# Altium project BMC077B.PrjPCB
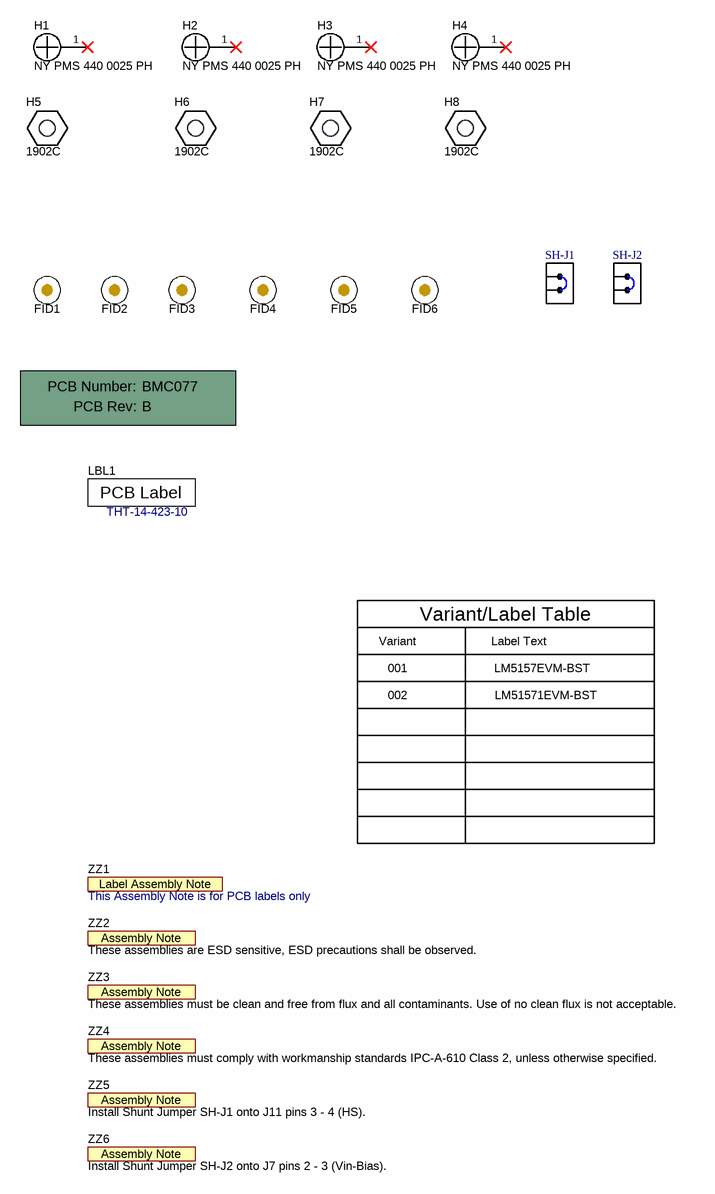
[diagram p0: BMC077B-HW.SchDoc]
TID: N/A; TechSupport: N/A; SCH_Rev: B; PRJ_Title: LM5157 EVM BOOST; PRJ_Number: BMC077; PRJ_Engineer: N/A; PRJ_Customer: Public Release; PCB_Rev: B; PCB_Layout: N/A; CopyrightYear: 2020
2 sheets, 103 parts. Net scope: global (net labels, ports and power ports of the same name join across sheets).
Board file: BMC077B.PcbDoc
Sheets:
  BMC077B-HW.SchDoc
  BMC077B.SchDoc

## Sheet BMC077B-HW.SchDoc: LM5157/51571/5158 EVM Hardware
size 431 x 279 mm; Date: Not shown in title block; ApprovedBy: Not shown in title block; CheckedBy: Not shown in title block; Author: Not shown in title block; CompanyName: Not shown in title block; Engineer: Not shown in title block; Organization: Not shown in title block; Address1: Not shown in title block; Address2: Not shown in title block; Address3: Not shown in title block; Address4: Not shown in title block; DocumentNumber: 1; Revision: Use project parameter SCH_Rev; SheetNumber: 1; SheetTotal: 2; PageSetup: Record=PageOptions¦CenterHorizontal=True¦CenterVertical=True¦PrintScale=1.00¦XCorrection=1.00¦YCorrection=1.00¦PrintKind=0¦BorderSize=5000000¦LeftOffset=0¦BottomOffset=0¦Orientation=2¦PaperLength=1000¦PaperWidth=1000¦Scale=100¦PaperSource=15¦PrintQuality=600¦MediaType=1¦DitherType=10¦PaperKind=Letter¦PrintScaleMode=1

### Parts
!PCB1  Printed Circuit Board  (value not drawn)  (mechanical)
FID1  Fiducial  [Fiducial10-20]  (value not drawn)
FID2  Fiducial  [Fiducial10-20]  (value not drawn)
FID3  Fiducial  [Fiducial10-20]  (value not drawn)
FID4  Fiducial  [Fiducial10-20]  (value not drawn)
FID5  Fiducial  [Fiducial10-20]  (value not drawn)
FID6  Fiducial  [Fiducial10-20]  (value not drawn)
H1  NY PMS 440 0025 PH  [NY PMS 440 0025 PH]
H2  NY PMS 440 0025 PH  [NY PMS 440 0025 PH]
H3  NY PMS 440 0025 PH  [NY PMS 440 0025 PH]
H4  NY PMS 440 0025 PH  [NY PMS 440 0025 PH]
H5  1902C  [Keystone_1902C]
H6  1902C  [Keystone_1902C]
H7  1902C  [Keystone_1902C]
H8  1902C  [Keystone_1902C]
LBL1  THT-14-423-10  [Label_650x200]
SH-J1  M7582-05  [Harwin_M7582-05]  (value not drawn)
SH-J2  M7582-05  [Harwin_M7582-05]  (value not drawn)
ZZ1  This Assembly Note is for PCB labels only  [AssemblyNoteLabel]  (no BOM)
ZZ2  These assemblies are ESD sensitive, ESD precautions shall be observed.  [AssemblyNote]  (no BOM)
ZZ3  These assemblies must be clean and free from flux and all contaminants. Use of no clean flux is not acceptable.  [AssemblyNote]  (no BOM)
ZZ4  These assemblies must comply with workmanship standards IPC-A-610 Class 2, unless otherwise specified.  [AssemblyNote]  (no BOM)
ZZ5  Install Shunt Jumper SH-J1 onto J11 pins 3 - 4 (HS).  [AssemblyNote]  (no BOM)
ZZ6  Install Shunt Jumper SH-J2 onto J7 pins 2 - 3 (Vin-Bias).  [AssemblyNote]  (no BOM)

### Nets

Not connected (* = marked no-connect by the designer): H1 1*; H2 1*; H3 1*; H4 1*

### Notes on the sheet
- Variant
- Variant/Label Table
- Label Text
- 001
- 002
- LM5157EVM-BST
- LM51571EVM-BST

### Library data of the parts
!PCB1 = CMP-0003618-2: Manufacturer: Any; PartNumber: BMC077
FID1-FID6 = CMP-0077181-1: Fiducial mark.  There is nothing to buy or mount.
H1-H4 = CMP-0003617-1: Machine Screw, Round, #4-40 x 1/4, Nylon, Philips panhead; Manufacturer: B&F Fastener Supply; CompType: Hardware
H5-H8 = CMP-0003610-1: Standoff, Hex, 0.5"L #4-40 Nylon; Manufacturer: Keystone; CompType: Hardware
LBL1 = CMP-0003625-1: Thermal Transfer Printable Labels, 0.650" W x 0.200" H - 10,000 per roll; Manufacturer: Brady; Note: Size: 0.65" x 0.20 "
SH-J1 SH-J2 = CMP-0078738-1: Single Operation 2.54mm Pitch Open Top Jumper Socket; Manufacturer: Harwin
ZZ1 = CMP-0003616-3
ZZ2 = CMP-0077236-1
ZZ3 = CMP-0077237-1
ZZ4 = CMP-0077238-1
ZZ5 ZZ6 = CMP-0077238-1: These assemblies must comply with workmanship standards IPC-A-610 Class 2, unless otherwise specified.

## Sheet BMC077B.SchDoc: LM5157/51571/5158 EVM Boost Converter
size 431 x 279 mm; Date: Not shown in title block; ApprovedBy: Not shown in title block; CheckedBy: Not shown in title block; Author: Not shown in title block; CompanyName: Not shown in title block; Engineer: Not shown in title block; Organization: Not shown in title block; Address1: Not shown in title block; Address2: Not shown in title block; Address3: Not shown in title block; Address4: Not shown in title block; DocumentNumber: 2; Revision: Use project parameter SCH_Rev; SheetNumber: 2; SheetTotal: 2; PageSetup: Record=PageOptions¦CenterHorizontal=True¦CenterVertical=True¦PrintScale=1.00¦XCorrection=1.00¦YCorrection=1.00¦PrintKind=0¦BorderSize=5000000¦LeftOffset=0¦BottomOffset=0¦Orientation=2¦PaperLength=1000¦PaperWidth=1000¦Scale=100¦PaperSource=15¦PrintQuality=600¦MediaType=1¦DitherType=10¦PaperKind=Letter¦PrintScaleMode=1
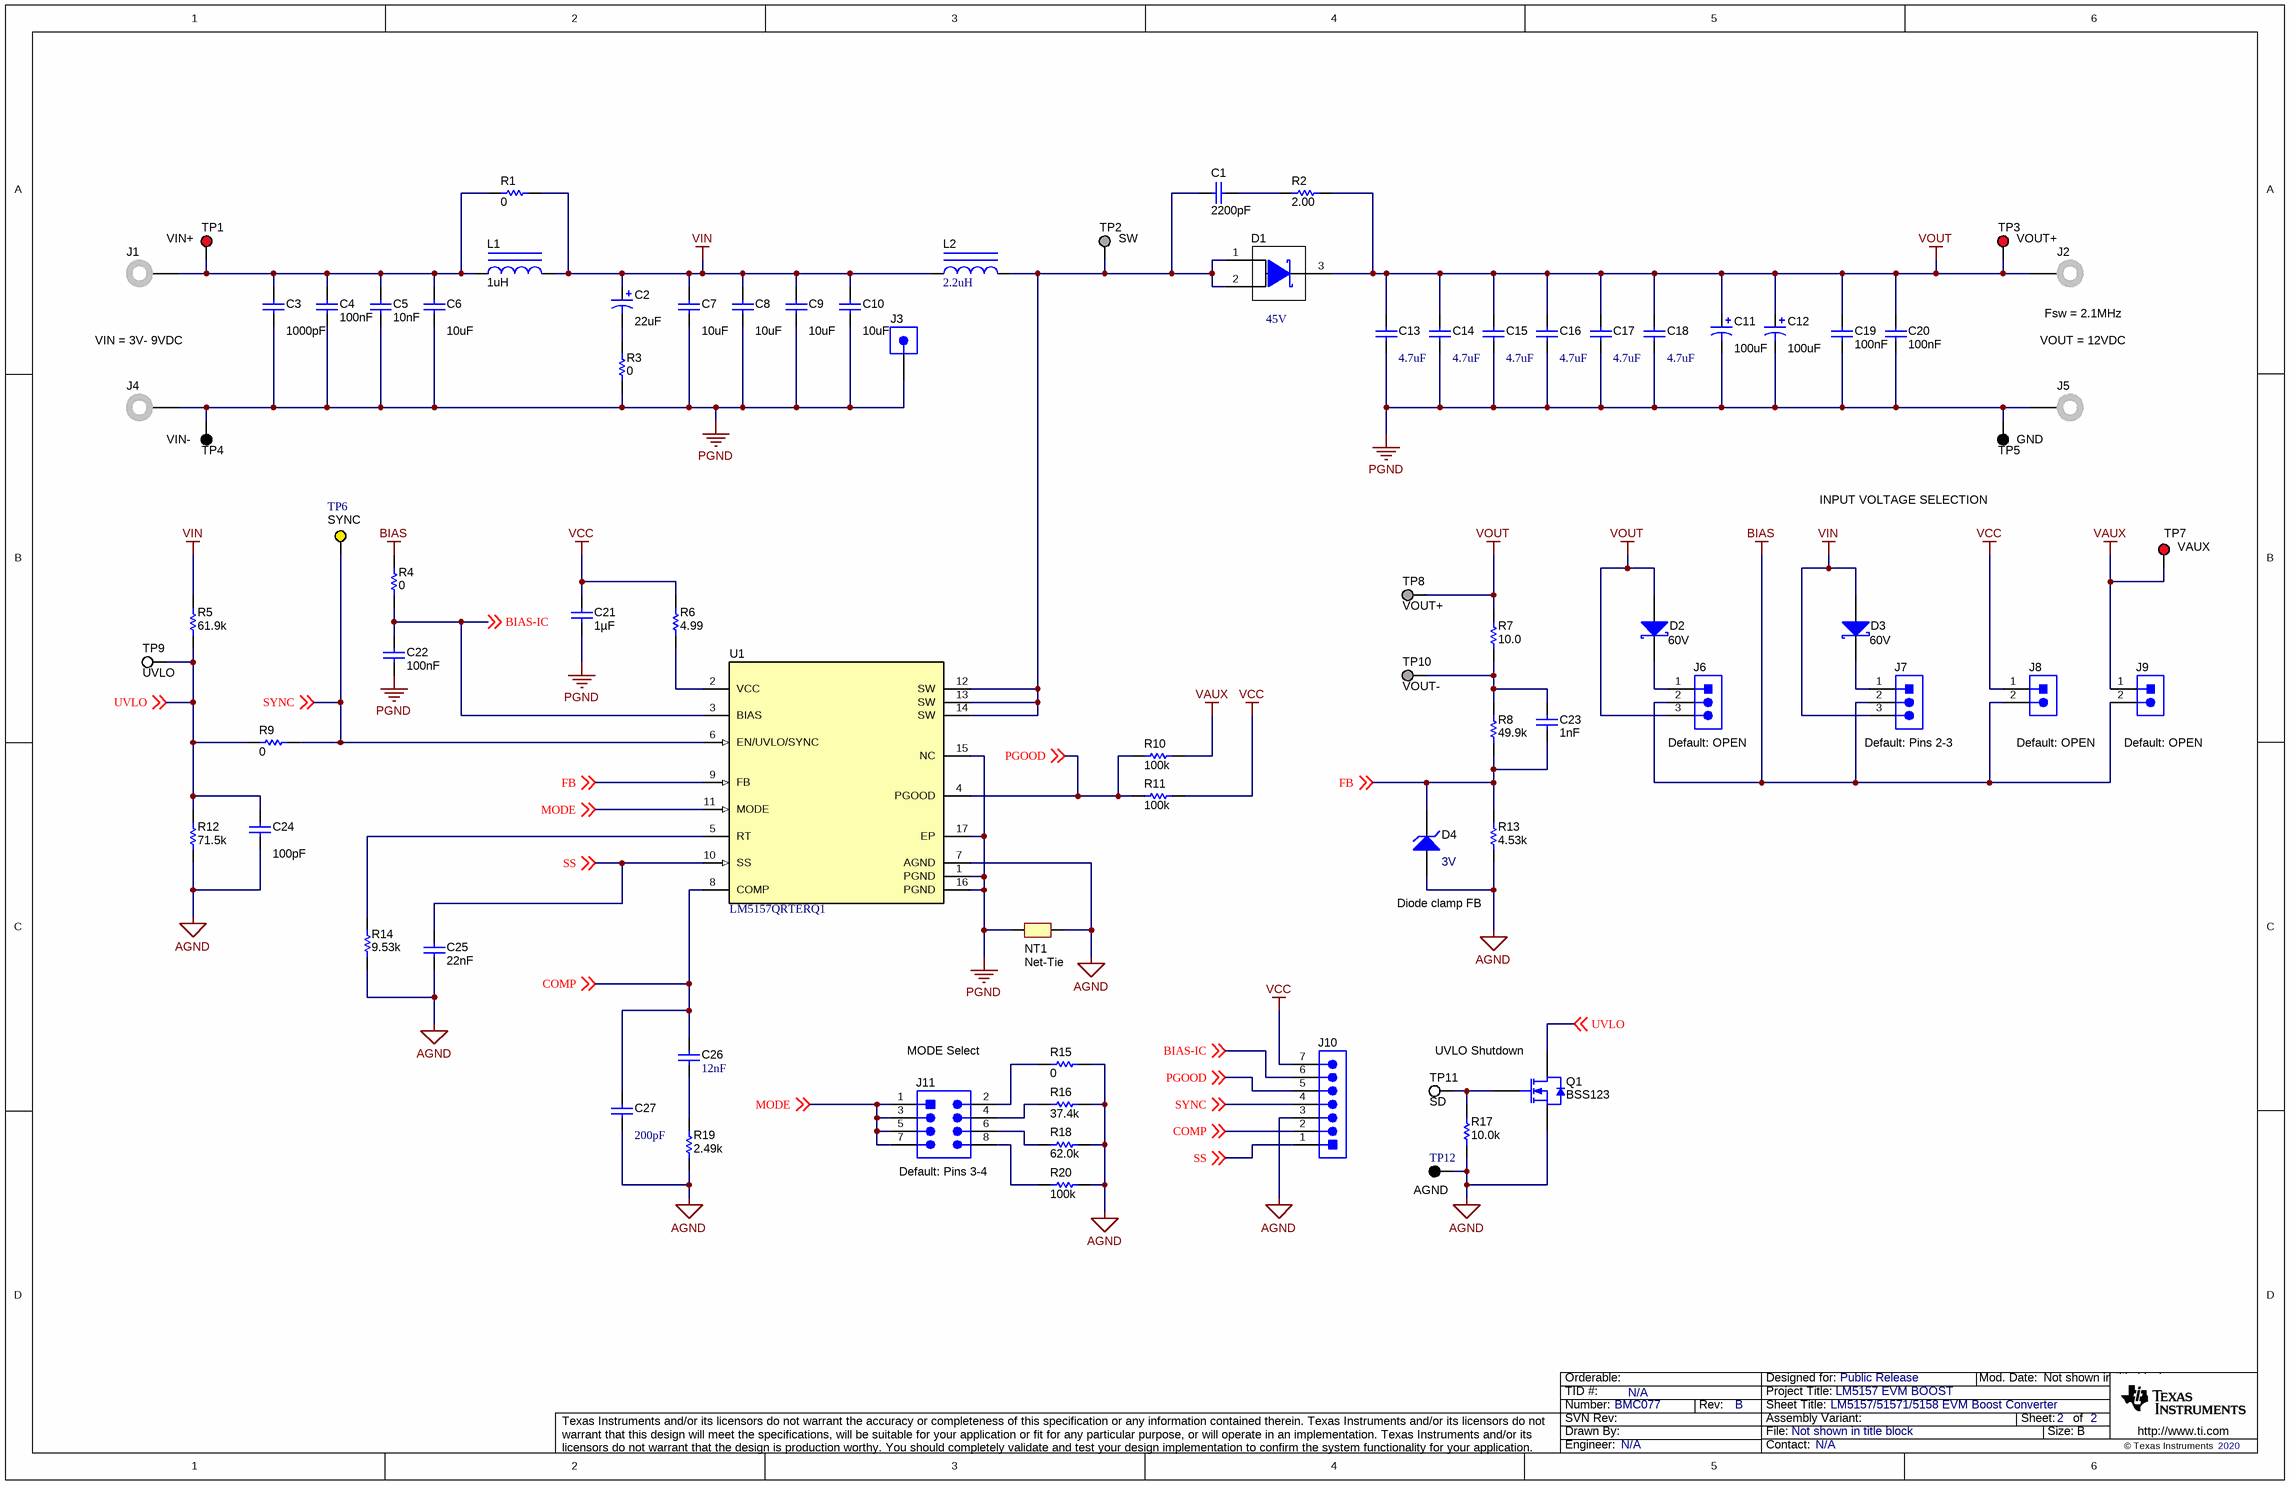
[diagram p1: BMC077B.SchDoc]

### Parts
C1  ValueDisplayed: 2200pF  [0603L]  (hidden comment: GRM188R72A222KA01D)
C2  ValueDisplayed: 22uF  [SM_RADIAL_F]  (hidden comment: EEE-FK2A220P)
C3  ValueDisplayed: 1000pF  [0603L]  (hidden comment: C0603X102K5RACTU)
C4  Cap_F: 100nF  [0603L]  (hidden comment: C0603C104K5RACAUTO)
C5  Cap_F: 10nF  [0603L]  (hidden comment: C0603X103K5RACTU)
C6  ValueDisplayed: 10uF  [1210_270]  (hidden comment: GRM32ER71H106KA12L)
C7  ValueDisplayed: 10uF  [1210_270]  (hidden comment: GRM32ER71H106KA12L)
C8  ValueDisplayed: 10uF  [1210_270]  (hidden comment: GRM32ER71H106KA12L)
C9  ValueDisplayed: 10uF  [1210_270]  (hidden comment: GRM32ER71H106KA12L)
C10  ValueDisplayed: 10uF  [1210_270]  (hidden comment: GRM32ER71H106KA12L)
C11  ValueDisplayed: 100uF  [Panasonic_G]  (hidden comment: EEH-ZC1H101P)
C12  ValueDisplayed: 100uF  [Panasonic_G]  (hidden comment: EEH-ZC1H101P)
C13  ValueDisplayed: 4.7uF  [1210_280]  (hidden comment: CGA6P3X7R1H475K250AB)
C14  ValueDisplayed: 4.7uF  [1210_280]  (hidden comment: CGA6P3X7R1H475K250AB)
C15  ValueDisplayed: 4.7uF  [1210_280]  (hidden comment: CGA6P3X7R1H475K250AB)
C16  ValueDisplayed: 4.7uF  [1210_280]  (hidden comment: CGA6P3X7R1H475K250AB)
C17  ValueDisplayed: 4.7uF  [1210_280]  (hidden comment: CGA6P3X7R1H475K250AB)
C18  ValueDisplayed: 4.7uF  [1210_280]  (hidden comment: CGA6P3X7R1H475K250AB)
C19  Cap_F: 100nF  [0603L]  (hidden comment: C0603C104K5RACAUTO)
C20  Cap_F: 100nF  [0603L]  (hidden comment: C0603C104K5RACAUTO)
C21  Cap_F: 1µF  [0603L]  (hidden comment: CGA3E1X7R1C105K080AC)
C22  Cap_F: 100nF  [0603L]  (hidden comment: GCJ188R72A104KA01D)
C23  Cap_F: 1nF  [0603L]  (hidden comment: CGA3E2X7R1H683K080AA)
C24  ValueDisplayed: 100pF  [0603L]  (hidden comment: C0603C101F5GACTU)
C25  Cap_F: 22nF  [0603L]  (hidden comment: C0603X223K5RACTU)
C26  Cap_F: 12nF  [0603L]  (hidden comment: C0603C123K5RACTU)
C27  ValueDisplayed: 200pF  [0603L]  (hidden comment: 06035A201FAT2A)
D1  value 45V  [SOT1289]  (hidden comment: PMEG045V100EPDAZ)
D2  value 60V  [SOD-123F]  (hidden comment: PMEG6010CEH,115)
D3  value 60V  [SOD-123F]  (hidden comment: PMEG6010CEH,115)
D4  value 3V  [SOD-323]  (hidden comment: MMSZ5225BS-7-F)
J1  575-8  [Keystone575-8]  (value not drawn)
J2  575-8  [Keystone575-8]  (value not drawn)
J3  1040  [CONN_1040]  (value not drawn)
J4  575-8  [Keystone575-8]  (value not drawn)
J5  575-8  [Keystone575-8]  (value not drawn)
J6  61300311121  [WURTH_61300311121]  (value not drawn)
J7  61300311121  [WURTH_61300311121]  (value not drawn)
J8  61300211121  [WURTH_61300211121]  (value not drawn)
J9  61300211121  [WURTH_61300211121]  (value not drawn)
J10  TSW-107-07-G-S  [TSW-107-XX-XXX-S]  (value not drawn)
J11  TSW-104-07-G-D  [TSW-104-07-G-D]  (value not drawn)
L1  ValueDisplayed: 1uH  [XAL7030]  (hidden comment: XAL7030-102MEB)
L2  ValueDisplayed: 2.2uH  [XEL6030_310]  (hidden comment: XEL6030-222MEB)
NT1  Net-Tie  [Net-Tie_10mil]  (net tie, no BOM)
Q1  BSS123  [SOT-23]
R1  ValueDisplayed: 0  [2512_WIDE_VISHAY]  (hidden comment: RCL12250000Z0EG)
R2  ValueDisplayed: 2.00  [1210]  (hidden comment: ERJ-14BQF2R0U)
R3  ValueDisplayed: 0  [0603L]  (hidden comment: RC0603JR-070RL)
R4  ValueDisplayed: 0  [0603L]  (hidden comment: RC0603JR-070RL)
R5  ValueDisplayed: 61.9k  [0603L]  (hidden comment: RC0603FR-0761K9L)
R6  ValueDisplayed: 4.99  [0603L]  (hidden comment: RC0603FR-074R99L)
R7  ValueDisplayed: 10.0  [0603L]  (hidden comment: RC0603FR-0710RL)
R8  ValueDisplayed: 49.9k  [0603L]  (hidden comment: RC0603FR-0749K9L)
R9  ValueDisplayed: 0  [0603L]  (hidden comment: RC0603JR-070RL)
R10  ValueDisplayed: 100k  [0603L]  (hidden comment: RC0603FR-07100KL)
R11  ValueDisplayed: 100k  [0603L]  (hidden comment: RC0603FR-07100KL)
R12  ValueDisplayed: 71.5k  [0603L]  (hidden comment: RC0603FR-0771K5L)
R13  ValueDisplayed: 4.53k  [0603L]  (hidden comment: RC0603FR-074K53L)
R14  ValueDisplayed: 9.53k  [0603L]  (hidden comment: RC0603FR-079K53L)
R15  ValueDisplayed: 0  [0603L]  (hidden comment: RC0603JR-070RL)
R16  ValueDisplayed: 37.4k  [0603L]  (hidden comment: RC0603FR-0737K4L)
R17  ValueDisplayed: 10.0k  [0603L]  (hidden comment: RC0603FR-0710KL)
R18  ValueDisplayed: 62.0k  [0603L]  (hidden comment: RC0603FR-0762KL)
R19  ValueDisplayed: 2.49k  [0603L]  (hidden comment: RC0603FR-072K49L)
R20  ValueDisplayed: 100k  [0603L]  (hidden comment: RC0603FR-07100KL)
TP1  VIN+  [Keystone5000]
TP2  SW  [Keystone_5017]  (no BOM)
TP3  VOUT+  [Keystone5000]
TP4  VIN-  [Keystone5001]
TP5  GND  [Keystone5001]
TP6  SYNC  [Keystone5004]
TP7  VAUX  [Keystone5000]
TP8  VOUT+  [TP_SM_1MM]  (no BOM)
TP9  UVLO  [Keystone5002]
TP10  VOUT-  [TP_SM_1MM]  (no BOM)
TP11  SD  [Keystone5002]
TP12  AGND  [Keystone5001]
U1  LM5157QRTERQ1  [RTE0016K]

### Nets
AGND: C24.2 C25.2 C27.2 D4.2(A) J10.3 NT1.2 Q1.2(S) R12.1 R13.1 R14.1 R15.2 R16.1 R17.1 R18.1 R19.1 R20.1 TP12.1 U1.7(AGND)
BIAS: J6.2 J7.2 J8.2 J9.2 R4.1
PGND: C3.2 C4.2 C5.2 C6.2 C7.2 C8.2 C9.2 C10.2 C11.2(-) C12.2(-) C13.2 C14.2 C15.2 C16.2 C17.2 C18.2 C19.2 C20.2 C21.1 C22.2 J3.1 J4.1 J5.1 NT1.1 R3.1 TP4.1 TP5.1 U1.1(PGND) U1.15(NC) U1.16(PGND) U1.17(EP)
VAUX: J9.1 R10.2 TP7.1
VCC: C21.2 J8.1 J10.7 R6.1 R11.2
VIN: C2.1(+) C7.1 C8.1 C9.1 C10.1 D3.2(A) J7.3 L1.2 L2.1 R1.2 R5.2
VOUT: C11.1(+) C12.1(+) C13.1 C14.1 C15.1 C16.1 C17.1 C18.1 C19.1 C20.1 D1.3(K) D2.2(A) J2.1 J6.3 R2.2 R7.2 TP3.1 TP8.1
BIAS-IC: C22.1 J10.6 R4.2 U1.3(BIAS) ; off-sheet BIAS-IC
COMP: C26.1 C27.1 J10.2 U1.8(COMP) ; off-sheet COMP
FB: C23.2 D4.1(K) R8.1 R13.2 U1.9(FB) ; off-sheet FB
MODE: J11.1 J11.3 J11.5 J11.7 U1.11(MODE) ; off-sheet MODE
PGOOD: J10.5 R10.1 R11.1 U1.4(PGOOD) ; off-sheet PGOOD
SS: C25.1 J10.1 U1.10(SS) ; off-sheet SS
SYNC: J10.4 R9.2 TP6.1 U1.6(EN/UVLO/SYNC) ; off-sheet SYNC
UVLO: C24.1 Q1.3(D) R5.1 R9.1 R12.2 TP9.1 ; off-sheet UVLO
NetC1_1: C1.1 R2.1
NetC1_2: C1.2 D1.1(A) D1.2(A) L2.2 TP2.1 U1.12(SW) U1.13(SW) U1.14(SW)
NetC2_2: C2.2(-) R3.2
NetC3_1: C3.1 C4.1 C5.1 C6.1 J1.1 L1.1 R1.1 TP1.1
NetC23_1: C23.1 R7.1 R8.2 TP10.1
NetC26_2: C26.2 R19.2
NetD2_1: D2.1(K) J6.1
NetD3_1: D3.1(K) J7.1
NetJ11_2: J11.2 R15.1
NetJ11_4: J11.4 R16.2
NetJ11_6: J11.6 R18.2
NetJ11_8: J11.8 R20.2
NetQ1_1: Q1.1(G) R17.2 TP11.1
NetR6_2: R6.2 U1.2(VCC)
NetR14_2: R14.2 U1.5(RT)

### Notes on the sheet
- VIN = 3V- 9VDC
- VOUT = 12VDC
- (near J2) Fsw = 2.1MHz
- INPUT VOLTAGE SELECTION
- (near J6) Default: OPEN
- (near J7) Default: Pins 2-3
- Default: OPEN
- (near J9) Default: OPEN
- Diode clamp FB
- MODE Select
- UVLO Shutdown
- (near J11) Default: Pins 3-4

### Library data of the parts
C1 = CMP-0007475-4: CAP, CERM, 2200 pF, 100 V, +/- 10%, X7R, 0603; Manufacturer: MuRata; Polarized: N; CompType: Capacitor; Value: 2200pF; U/M: EA; Cap_F: 2.2nF; Value1: Unknown; VDC_V: 100V; TaMin_C: -55°C; TaMax_C: 125°C; Cap_Case: 0603; SizeArea_mm2: 1.28; SizeAreaWB_mm2: 4.68; SizeX_mm: 1.6; SizeY_mm: 0.8; SizeZ_mm: 1; AEC Category: Q200
C2 = CMP-0011202-2: CAP, AL, 22 uF, 100 V, +/- 20%, 1.3 ohm, AEC-Q200 Grade 2, SMD; Manufacturer: Panasonic; TaMin_C: -55°C; ESR_ohm: 1.3; Polarized: Y; SizeAreaWB_mm2: 123.6; Value1: 1.3 ohm; U/M: EA; Value: 22uF; TaMax_C: 105°C; SizeZ_mm: 10.2; SizeX_mm: 10; SizeY_mm: 8.3; Cap_Case: F; Value2: 100V; SizeArea_mm2: 83; CompType: Capacitor; Cap_F: 22µF; IRMS_A: 130mA; AEC Grade: 2; AEC Category: Q200
C3 = CMP-0006976-5: CAP, CERM, 1000 pF, 50 V, +/- 10%, X7R, 0603; Manufacturer: Kemet; TaMin_C: -55°C; Polarized: N; SizeAreaWB_mm2: 4.68; Value1: Unknown; U/M: EA; Value: 1000pF; TaMax_C: 125°C; SizeZ_mm: 1; SizeX_mm: 1.6; SizeY_mm: 0.8; Cap_Case: 0603; Value2: 50V; SizeArea_mm2: 1.28; CompType: Capacitor; Cap_F: 1nF; AEC Category: Q200
C4 C19 C20 = CMP-0079602-1: CAP, CERM, 0.1 µF, 50 V,+/- 10%, X7R, AEC-Q200 Grade 1, 0603; Manufacturer: Kemet; TaMin_C: -55°C; Polarized: N; SizeAreaWB_mm2: 4.68; U/M: EA; Value: 0.1uF; TaMax_C: 125°C; SizeZ_mm: 1; SizeX_mm: 1.6; SizeY_mm: 0.8; Cap_Case: 0603; Value2: 50V; SizeArea_mm2: 1.28; AEC Qualified: Y; AEC Category: Q200; ValueDisplayed: 0.1µF
C5 = CMP-0006978-4: CAP, CERM, 0.01 uF, 50 V, +/- 10%, X7R, 0603; Manufacturer: Kemet; TaMin_C: -55°C; Polarized: N; SizeAreaWB_mm2: 4.68; Value1: Unknown; U/M: EA; Value: 0.01uF; TaMax_C: 125°C; SizeZ_mm: 1; SizeX_mm: 1.6; SizeY_mm: 0.8; Cap_Case: 0603; Value2: 50V; SizeArea_mm2: 1.28; AEC Category: Q200
C6 C9 C10 = CMP-0009226-3: CAP, CERM, 10 uF, 50 V, +/- 10%, X7R, 1210; Manufacturer: MuRata; TaMin_C: -55°C; Polarized: N; SizeAreaWB_mm2: 14.7; Value1: Unknown; U/M: EA; Value: 10uF; TaMax_C: 125°C; SizeZ_mm: 2.7; SizeX_mm: 3.2; SizeY_mm: 2.5; Cap_Case: 1210; Value2: 50V; SizeArea_mm2: 8; Cap_F: 10µF; AEC Category: Q200
C7 C8 = CMP-0009226-3: CAP, CERM, 10 uF, 50 V, +/- 10%, X7R, 1210; Manufacturer: MuRata; TaMin_C: -55°C; Polarized: N; SizeAreaWB_mm2: 14.7; Value1: Unknown; U/M: EA; Value: 10uF; TaMax_C: 125°C; SizeZ_mm: 2.7; SizeX_mm: 3.2; SizeY_mm: 2.5; Cap_Case: 1210; Value2: 50V; SizeArea_mm2: 8; CompType: Capacitor; Cap_F: 10µF; AEC Category: Q200
C11 C12 = CMP-0064994-2: CAP, Polymer Hybrid, 100 uF, 50 V,+/- 20%, 0.028 ohm, AEC-Q200 Grade 1, D10xL10.2mm SMD; Manufacturer: Panasonic; TaMin_C: -55°C; ESR_ohm: 0.028; Polarized: Y; SizeAreaWB_mm2: 151.29; Value: 100uF; TaMax_C: 125°C; SizeZ_mm: 10.5; SizeX_mm: 10.3; Cap_Case: 10x10.2mm; Value2: 50V; SizeArea_mm2: 106.09; CompType: Capacitor; Cap_F: 100µF; IRMS_A: 1.6A; AEC Grade: 1; AEC Category: Q200
C13-C18 = CMP-0009162-2: CAP, CERM, 4.7 uF, 50 V, +/- 10%, X7R, AEC-Q200 Grade 1, 1210; Manufacturer: TDK; TaMin_C: -55°C; ESR_ohm: 3.166m; Polarized: N; SizeAreaWB_mm2: 14.7; Value1: 0.003166 ohm; U/M: EA; Value: 4.7uF; TaMax_C: 125°C; SizeZ_mm: 2.8; SizeX_mm: 3.2; SizeY_mm: 2.5; Value2: 50V; SizeArea_mm2: 8; AEC Qualified: Y; Cap_F: 4.7µF; IRMS_A: 4.13311A; AEC Grade: 1; AEC Category: Q200
C21 = CMP-0079607-1: CAP, CERM, 1 µF, 16 V,+/- 10%, X7R, AEC-Q200 Grade 1, 0603; Manufacturer: TDK; TaMin_C: -55°C; Polarized: N; SizeAreaWB_mm2: 4.68; U/M: EA; Value: 1uF; TaMax_C: 125°C; SizeZ_mm: 1; SizeX_mm: 1.6; SizeY_mm: 0.8; Cap_Case: 0603; Value2: 16V; SizeArea_mm2: 1.28; AEC Qualified: Y; AEC Category: Q200
C22 = CMP-0064935-4: CAP, CERM, 0.1 uF, 100 V,+/- 10%, X7R, AEC-Q200 Grade 1, 0603; Manufacturer: MuRata; TaMin_C: -55°C; Polarized: N; SizeAreaWB_mm2: 4.68; Value1: Unknown; U/M: EA; Value: 0.1uF; TaMax_C: 125°C; SizeZ_mm: 1; SizeX_mm: 1.6; SizeY_mm: 0.8; Cap_Case: 0603; Value2: 100V; SizeArea_mm2: 1.28; AEC Qualified: Y; AEC Category: Q200
C23 = CMP-0007080-5: CAP, CERM, 0.068 uF, 50 V, +/- 10%, X7R, AEC-Q200 Grade 1, 0603; Manufacturer: TDK; TaMin_C: -55°C; Polarized: N; SizeAreaWB_mm2: 4.68; Value1: 0.035979 ohm; U/M: EA; TaMax_C: 125°C; SizeZ_mm: 1; SizeX_mm: 1.6; SizeY_mm: 0.8; Cap_Case: 0603; Value2: 50V; SizeArea_mm2: 1.28; AEC Qualified: Y; AEC Category: Q200; ESR_ohm: 0.035979; IRMS_A: 886.483mA
C24 = CMP-0080091-1: CAP, CERM, 100 pF, 50 V,+/- 1%, C0G/NP0, 0603; Manufacturer: Kemet; TaMin_C: -55°C; Polarized: N; SizeAreaWB_mm2: 4.68; U/M: EA; Value: 100pF; TaMax_C: 125°C; SizeZ_mm: 1; SizeX_mm: 1.6; SizeY_mm: 0.8; Cap_Case: 0603; Value2: 50V; SizeArea_mm2: 1.28; CompType: Capacitor; AEC Category: Q200; Green_REACh: Passed; Green_Lifecycle: Active
C25 = CMP-0006984-4: CAP, CERM, 0.022 uF, 50 V, +/- 10%, X7R, 0603; Manufacturer: Kemet; TaMin_C: -55°C; Polarized: N; SizeAreaWB_mm2: 4.68; Value1: Unknown; U/M: EA; TaMax_C: 125°C; SizeZ_mm: 1; SizeX_mm: 1.6; SizeY_mm: 0.8; Cap_Case: 0603; Value2: 50V; SizeArea_mm2: 1.28; AEC Category: Q200
C26 = CMP-0084236-1: CAP, CERM, 0.012 µF, 50 V,+/- 10%, X7R, AEC-Q200 Grade 1, 0603; Manufacturer: Kemet; TaMin_C: -55°C; Polarized: N; SizeAreaWB_mm2: 4.68; U/M: EA; Value: 0.012uF; TaMax_C: 125°C; SizeZ_mm: 1; SizeX_mm: 1.6; SizeY_mm: 0.8; Cap_Case: 0603; Value2: 50V; SizeArea_mm2: 1.28; AEC Qualified: Y; AEC Category: Q200
C27 = CMP-0080089-1: CAP, CERM, 200 pF, 50 V,+/- 1%, C0G/NP0, 0603; Manufacturer: AVX; SizeAreaWB_mm2: 4.68; SizeArea_mm2: 1.28; AEC Qualified: N; AEC Category: Q200; Value: 200pF; TaMax_C: 125°C; SizeZ_mm: 1; Green_REACh: Incomplete; TaMin_C: -55°C; VDC_V: 50V; SizeY_mm: 0.8; Green_Lifecycle: Active; U/M: EA; SizeX_mm: 1.6; Cap_Case: 0603
D1 = CMP-0083733-3: Diode, Schottky, 45 V, 10 A, AEC-Q101, CFP15; Manufacturer: Nexperia; Value1: 10A; SizeX_mm: 6.5; TJmax_C: 175°C; SizeAreaWB_mm2: 53.55; SizeArea_mm2: 27.95; Value2: 0.49V; SizeZ_mm: 0.82; AEC Category: Q101; SizeY_mm: 4.3; AEC Qualified: Y; Vf_V: 490mV
D2 D3 = CMP-0028377-2: Diode, Schottky, 60 V, 1 A, SOD-123F; Manufacturer: Nexperia; Io_A: 1A; Green_Lifecycle: Not Set; SizeAreaWB_mm2: 11.7; Green_REACh: Incomplete; TJmax_C: 150°C; SizeZ_mm: 1.1; SizeX_mm: 3.5; SizeY_mm: 1.6; Vf_V: 570mV; Value2: 0.57V; SizeArea_mm2: 5.6; AEC Category: Q101
D4 = CMP-0005848-3: Diode, Zener, 3 V, 200 mW, SOD-323; Manufacturer: Diodes Inc.; Power_W: 200mW; SizeAreaWB_mm2: 8.695; Value1: 0.2W; RJA_CperW: 350; SizeZ_mm: 1; SizeX_mm: 2.7; SizeY_mm: 1.35; SizeArea_mm2: 3.645; AEC Category: Q101
J1 J2 J4 J5 = CMP-0055166-2: Standard Banana Jack, Uninsulated, 8.9mm; Manufacturer: Keystone; CT: TRUE; Green_REACh: Passed; CNHeader: FALSE; Green_Lifecycle: Active
J3 = CMP-0055161-1: TEST POINT SLOTTED .118", TH; Manufacturer: Keystone; CNHeader: FALSE; Green_Lifecycle: Active; Green_REACh: Passed; CT: TRUE
J6 J7 = CMP-0054796-2: Header, 2.54 mm, 3x1, Gold, TH; Manufacturer: Wurth Elektronik; Cert_UL: Y; Gender: Male; Green_Lifecycle: Active; Green_REACh: Passed; Pitch_mm: 2.54; Row_Count: 1; Shrouded: N
J8 J9 = CMP-0054794-2: Header, 2.54 mm, 2x1, Gold, TH; Manufacturer: Wurth Elektronik; Cert_UL: Y; Gender: Male; Green_Lifecycle: Active; Green_REACh: Passed; Pitch_mm: 2.54; Row_Count: 1; Shrouded: N
J10 = CMP-0075416-1: Header, 100mil, 7x1, Gold, TH; Manufacturer: Samtec; Pitch_mm: 2.54; Cert_VDE: N; Gender: Male; Cert_CSA: Y; Voltage_V: 550V; Green_REACh: Passed; Current_A: 6.3A; CT: False; Green_Lifecycle: Active; Row_Count: 1; CNHeader: True
J11 = CMP-0075408-3: Header, 100mil, 4x2, Gold, TH; Manufacturer: Samtec; Pitch_mm: 2.54; Cert_VDE: N; Gender: Male; Cert_CSA: Y; Voltage_V: 550V; Green_REACh: Passed; Current_A: 6.3A; Green_Lifecycle: Active; Row_Count: 2
L1 = CMP-0061033-1: Inductor, Shielded, Composite, 1 uH, 21.8 A, 0.00455 ohm, SMD; Manufacturer: Coilcraft; Isat: 28A @ 0.7% inductance drop; Irms: 21.8A @ 40C rise; Green_Lifecycle: Not Set; SizeAreaWB_mm2: 100; DCR_ohm: 4.55m; Green_REACh: Incomplete; Value: 1uH; Imax_A: 21.8A; SizeZ_mm: 3.1; SizeX_mm: 8; SizeArea_mm2: 64; Ind_H: 1µH; AEC Category: Q200
L2 = CMP-0061100-1: Inductor, Shielded, Composite, 2.2 uH, 10 A, 0.01397 ohm, AEC-Q200 Grade 1, SMD; Manufacturer: Coilcraft; Isat: 12.6A @ 30% inductance drop; Irms: 10A @ 40C rise; SizeAreaWB_mm2: 71.5616; Value: 2.2uH; Imax_A: 10A; SizeZ_mm: 3.1; SizeX_mm: 6.36; SizeY_mm: 6.56; SizeArea_mm2: 41.7216; Ind_H: 2.2µH; AEC Qualified: Y; AEC Grade: 1; AEC Category: Q200
NT1 = CMP-0078142-4: Single point connection between nets.
Q1 = CMP-0000947-2: MOSFET, N-CH, 100 V, 0.17 A, SOT-23; Alternate Manufacturer: None; Manufacturer: Fairchild Semiconductor; SizeZ_mm: 1.1; ChType: N; Value2: 1.8 nC; Value1: 1; VdsMax_V: 100V; SizeX_mm: 2.5; SizeY_mm: 3; Vgs_V: 20V; Value: 100V; Rdson45_ohm: 10; SizeArea_mm2: 7.5; AEC Category: Q101; IdsMax_A: 1.7dA; SizeAreaWB_mm2: 14; U/M: EA; QgTyp_nC: 1.8
R1 = CMP-0015368-2: RES, 0, 5%, 2 W, 2512 WIDE; Manufacturer: Vishay Draloric; Power_W: 2W; TempCo: ppm/C; Value_Code: 0000; U/M: EA; Value: 0; EIA_Code: E24; AEC Category: Q200
R2 = CMP-0015029-2: RES, 2.00, 1%, 0.5 W, AEC-Q200 Grade 0, 1210; Manufacturer: Panasonic; Power_W: 500mW; TempCo: 100 ppm/C; SizeAreaWB_mm2: 14.7; Value_Code: 2R00; U/M: EA; Value: 2.00; EIA_Code: E96; Res_ohm: 2; SizeX_mm: 3.2; SizeY_mm: 2.5; SizeZ_mm: 1.35; Value2: 0.5W; SizeArea_mm2: 8; AEC Qualified: Y; AEC Grade: 0; AEC Category: Q200
R3 R4 R9 R15 = CMP-0025885-5: RES, 0, 5%, 0.1 W, 0603; Manufacturer: Yageo; Power_W: 100mW; TempCo: 200 ppm/C; Value_Code: 0000; Value: 0; EIA_Code: E24; SizeX_mm: 1.6; SizeY_mm: 0.8; SizeZ_mm: 1; Value2: 0.1W; SizeArea_mm2: 1.28; AEC Qualified: N; VDC_V: 75V; AEC Category: Q200; SizeAreaWB_mm2: 4.68
R5 = CMP-0023216-5: RES, 61.9 k, 1%, 0.1 W, 0603; Manufacturer: Yageo; Power_W: 100mW; TempCo: 100 ppm/C; Value_Code: 61k9; Value: 61.9k; EIA_Code: E96; SizeX_mm: 1.6; SizeY_mm: 0.8; SizeZ_mm: 1; Value2: 0.1W; SizeArea_mm2: 1.28; AEC Qualified: N; VDC_V: 75V; AEC Category: Q200; SizeAreaWB_mm2: 4.68
R6 = CMP-0023161-5: RES, 4.99, 1%, 0.1 W, 0603; Manufacturer: Yageo; Power_W: 100mW; TempCo: 200 ppm/C; Value_Code: 4R99; Value: 4.99; EIA_Code: E96; SizeX_mm: 1.6; SizeY_mm: 0.8; SizeZ_mm: 1; Value2: 0.1W; SizeArea_mm2: 1.28; AEC Qualified: N; VDC_V: 75V; AEC Category: Q200; SizeAreaWB_mm2: 4.68
R7 = CMP-0022751-4: RES, 10.0, 1%, 0.1 W, 0603; Manufacturer: Yageo; Power_W: 100mW; TempCo: 100 ppm/C; Value_Code: 10R0; Value: 10.0; EIA_Code: E96; Res_ohm: 10; SizeX_mm: 1.6; SizeY_mm: 0.8; SizeZ_mm: 1; Value2: 0.1W; SizeArea_mm2: 1.28; AEC Qualified: N; VDC_V: 75V; AEC Category: Q200; SizeAreaWB_mm2: 4.68
R8 = CMP-0023142-5: RES, 49.9 k, 1%, 0.1 W, 0603; Manufacturer: Yageo; Power_W: 100mW; TempCo: 100 ppm/C; Value_Code: 49k9; Value: 49.9k; EIA_Code: E96; SizeX_mm: 1.6; SizeY_mm: 0.8; SizeZ_mm: 1; Value2: 0.1W; SizeArea_mm2: 1.28; AEC Qualified: N; VDC_V: 75V; AEC Category: Q200; SizeAreaWB_mm2: 4.68
R10 R11 R20 = CMP-0022735-5: RES, 100 k, 1%, 0.1 W, 0603; Manufacturer: Yageo; Power_W: 100mW; TempCo: 100 ppm/C; Value: 100k; EIA_Code: E96; SizeX_mm: 1.6; SizeY_mm: 0.8; SizeZ_mm: 1; Value2: 0.1W; SizeArea_mm2: 1.28; AEC Qualified: N; VDC_V: 75V; AEC Category: Q200; SizeAreaWB_mm2: 4.68
R12 = CMP-0023259-5: RES, 71.5 k, 1%, 0.1 W, 0603; Manufacturer: Yageo; Power_W: 100mW; TempCo: 100 ppm/C; Value_Code: 71k5; Value: 71.5k; EIA_Code: E96; SizeX_mm: 1.6; SizeY_mm: 0.8; SizeZ_mm: 1; Value2: 0.1W; SizeArea_mm2: 1.28; AEC Qualified: N; VDC_V: 75V; AEC Category: Q200; SizeAreaWB_mm2: 4.68
R13 = CMP-0023150-5: RES, 4.53 k, 1%, 0.1 W, 0603; Manufacturer: Yageo; Power_W: 100mW; TempCo: 100 ppm/C; Value_Code: 4k53; Value: 4.53k; EIA_Code: E96; SizeX_mm: 1.6; SizeY_mm: 0.8; SizeZ_mm: 1; Value2: 0.1W; SizeArea_mm2: 1.28; AEC Qualified: N; VDC_V: 75V; AEC Category: Q200; SizeAreaWB_mm2: 4.68
R14 = CMP-0023335-5: RES, 9.53 k, 1%, 0.1 W, 0603; Manufacturer: Yageo; Power_W: 100mW; TempCo: 100 ppm/C; Value_Code: 9k53; Value: 9.53k; EIA_Code: E96; SizeX_mm: 1.6; SizeY_mm: 0.8; SizeZ_mm: 1; Value2: 0.1W; SizeArea_mm2: 1.28; AEC Qualified: N; VDC_V: 75V; AEC Category: Q200; SizeAreaWB_mm2: 4.68
R16 = CMP-0023062-5: RES, 37.4 k, 1%, 0.1 W, 0603; Manufacturer: Yageo; Power_W: 100mW; TempCo: 100 ppm/C; Value_Code: 37k4; Value: 37.4k; EIA_Code: E96; SizeX_mm: 1.6; SizeY_mm: 0.8; SizeZ_mm: 1; Value2: 0.1W; SizeArea_mm2: 1.28; AEC Qualified: N; VDC_V: 75V; AEC Category: Q200; SizeAreaWB_mm2: 4.68
R17 = CMP-0022746-5: RES, 10.0 k, 1%, 0.1 W, 0603; Manufacturer: Yageo; Power_W: 100mW; TempCo: 100 ppm/C; Value_Code: 10k0; Value: 10.0k; EIA_Code: E96; Res_ohm: 10k; SizeX_mm: 1.6; SizeY_mm: 0.8; SizeZ_mm: 1; Value2: 0.1W; SizeArea_mm2: 1.28; AEC Qualified: N; VDC_V: 75V; AEC Category: Q200; SizeAreaWB_mm2: 4.68
R18 = CMP-0023220-5: RES, 62.0 k, 1%, 0.1 W, 0603; Manufacturer: Yageo; Power_W: 100mW; TempCo: 100 ppm/C; Value_Code: 62k0; Value: 62.0k; Res_ohm: 62k; SizeX_mm: 1.6; SizeY_mm: 0.8; SizeZ_mm: 1; Value2: 0.1W; SizeArea_mm2: 1.28; AEC Qualified: N; VDC_V: 75V; AEC Category: Q200; SizeAreaWB_mm2: 4.68
R19 = CMP-0022990-5: RES, 2.49 k, 1%, 0.1 W, 0603; Manufacturer: Yageo; Power_W: 100mW; TempCo: 100 ppm/C; Value_Code: 2k49; Value: 2.49k; EIA_Code: E96; SizeX_mm: 1.6; SizeY_mm: 0.8; SizeZ_mm: 1; Value2: 0.1W; SizeArea_mm2: 1.28; AEC Qualified: N; VDC_V: 75V; AEC Category: Q200; SizeAreaWB_mm2: 4.68
TP1 TP3 TP7 = CMP-0055137-1: Test Point, Miniature, Red, TH; Manufacturer: Keystone; PartNumber: 5000; CNHeader: FALSE; Green_Lifecycle: Active; Green_REACh: Passed; ContactFinish: Silver; CT: TRUE
TP2 = CMP-0078225-1: PC Test Point, SMT; Manufacturer: Keystone; PartNumber: 5017
TP4 TP5 = CMP-0055138-1: Test Point, Miniature, Black, TH; Manufacturer: Keystone; PartNumber: 5001; CNHeader: FALSE; Green_Lifecycle: Active; Green_REACh: Passed; ContactFinish: Silver; CT: TRUE
TP6 = CMP-0055141-1: Test Point, Miniature, Yellow, TH; Manufacturer: Keystone; CNHeader: FALSE; Green_Lifecycle: Active; Green_REACh: Passed; ContactFinish: Silver; CT: TRUE
TP8 TP10 = CMP-0003825-1: 1mm Test Point, SMT; Manufacturer: Any
TP9 TP11 = CMP-0055139-1: Test Point, Miniature, White, TH; Manufacturer: Keystone; PartNumber: 5002; CNHeader: FALSE; Green_Lifecycle: Active; Green_REACh: Passed; ContactFinish: Silver; CT: TRUE
TP12 = CMP-0055138-1: Test Point, Miniature, Black, TH; Manufacturer: Keystone; CNHeader: FALSE; Green_Lifecycle: Active; Green_REACh: Passed; ContactFinish: Silver; CT: TRUE
U1 = CMP-0861102-1: 2.2MHz Wide VIN Boost/Sepic/Flyback Converter with Dual Random Spread Spectrum, RTE0016K (WQFN-16); Alternate Manufacturer: Texas Instruments; SizeX_mm: 3; SizeZ_mm: 0.8; SizeArea_mm2: 9; SizeAreaWB_mm2: 16; AEC Category: Q200; CompType: IC; AEC Qualified: N

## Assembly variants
001: not fitted C1 C11 C12 C23 C24 D4 FID1 FID2 FID3 FID4 FID5 FID6 L1 R2 R10
002: not fitted C1 C11 C12 C23 C24 D4 FID1 FID2 FID3 FID4 FID5 FID6 L1 R2 R10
